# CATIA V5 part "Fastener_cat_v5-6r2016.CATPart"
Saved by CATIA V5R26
Part number: Fastener
Bounding box of the stored display mesh (mm): x -5 to 5, y -5 to 5, z -48 to 0
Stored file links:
  D:\_Deepak\CATIA\CATIA V5 2015 Parts Files\Tutorial Files\Tutorials\c14_catia_v5_6r2016_tut\c14tut2\c14tut2.CATParts\Fastener_cat_v5-6r2016.CATPart
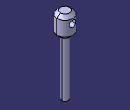
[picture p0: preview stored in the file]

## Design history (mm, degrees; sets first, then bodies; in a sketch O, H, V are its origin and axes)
Body1 (main body)
  Sketch1 on xy-plane, origin (0, 0, 0), H (1, 0, 0), V (0, 1, 0)
    circle A1 centre (0, 0) radius 5
    circle A2 centre (0, 0) radius 2
    radius A2 = 2
    radius A1 = 5
  MultiPad1: profile Sketch1, domains (length 0 / length 48; length 0 / length 13)
  Chamfer1: length 2, angle 45, on 2 edges
  Chamfer2: length 0.508, angle 45, on 1 edge
  Sketch2 on zx-plane, origin (-1.612, 0, 1.612), H (1, 0, 0), V (0, 0, -1)
    point P1 (1.612, 6.35)
    reference intersected line E1 through (1.612, 0) direction (0, 1) from yz-plane
    distance P1 H = 6.35
    coincidence: E1 P1
  Hole1: placed by Sketch2, at (0, 0, -4.738) direction (0, -1, 0), diameter 4, depth 10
